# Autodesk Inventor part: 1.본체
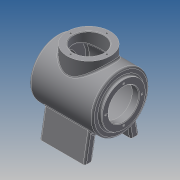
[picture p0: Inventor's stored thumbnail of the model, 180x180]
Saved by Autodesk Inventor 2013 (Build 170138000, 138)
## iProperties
Created: 2015-01
Part Number: 1.본체
Material: Generic
Document SubType Name: Modeling
Designer: kb543-154
Density: 1 g/cm^3
Author: kb543-154
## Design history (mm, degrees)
sketch "스케치1"
  geometry: L1 (-61, 0)-(-61, 38); L2 (-61, 38)-(-56, 38); L3 (-56, 38)-(-56, 50); L4 (-56, 50)-(56, 50); L5 (56, 50)-(56, 38); L6 (56, 38)-(61, 38); L7 (61, 38)-(61, 0); L8 (61, 0)-(-61, 0); 2 further points
  constraints: 16 end point, 5 parallel, 1 coincident, 1 collinear, 1 midpoint, 1 perpendicular, 1 vertical
  dimensions: "d0" = 76 diameter of L2 L8; "d2" = 100 diameter of L4 L8; "d3" = 76 diameter of L6 L8; "d4" = 112 distance of L3.end L4.end; "d5" = 122 distance of L7.end L1.start; "d6" = 5 distance of L1.end L2.end
revolve "회전1" sketch "스케치1" stored, may be unused: angle "d7" = 90 deg
sketch "스케치2"
  geometry: L1 (-61, -38)-(-61, 38) reference; L2 (61, -38)-(61, 38) reference; L3 (-61, 0)-(61, 0); L4 (-61, 27)-(-49, 27); L5 (-56, -50)-(-56, 50) reference; L6 (-49, 27)-(-49, 45); L7 (-49, 45)-(48, 45); L8 (48, 45)-(48, 27); L9 (48, 27)-(61, 27); L10 (56, -50)-(56, 50) reference; 1 further point
  constraints: 12 end point, 3 perpendicular, 2 midpoint, 2 point on line, 1 collinear, 1 parallel, 1 vertical
  dimensions: "d8" = 54 diameter of L4 L3; "d10" = 90 diameter of L7 L3; "d11" = 97 distance between parallel lines of L8 L6; "d12" = 7 horizontal distance of L6.end L5.end
revolve "회전2" sketch "스케치2" stored, may be unused: angle "d13" = 90 deg
sketch "스케치3"
  geometry: L1 (-39.336, -30.865)-(-48, -80); L2 (-48, -80)-(-34, -80); L3 (-34, -80)-(-27.282, -41.901); L4 (27.282, -41.901)-(34, -80); L5 (34, -80)-(48, -80); L6 (48, -80)-(39.336, -30.865); L7 (0, 50)-(0, -50); L8 (-50.903, 0)-(50, 0); 5 further points
  constraints: 16 end point, 3 midpoint, 2 collinear, 2 perpendicular, 1 coincident, 1 horizontal, 1 parallel, 8 other
  dimensions: "d24" = 80 distance from line of L2 point (0, 0); "d25" = 14 distance of L1.end L2.end; "d26" = 14 distance of L4.end L5.end; "d28" = 80 deg angle of L5 L4; "d29" = 100 deg angle of L5 L6; "d30" = 80 deg angle of L2 L3; "d31" = 100 deg angle of L1 L2 (derived); "d32" = 80 distance between parallel lines of L8 L5; "d34" = 69.72143 distance from line of L8.start L4; "d95" = 48 horizontal distance of point (0, 0) L1.end; "d96" = 48 horizontal distance of point (0, 0) L5.end
extrude "돌출1" join sketch "스케치3" stored distance "d35" = 80; taper "d36" = 0 deg
node "작업 평면2"
sketch "스케치7"
  geometry: L1 (21, -10)-(21, -86) reference; C1 r 38 at (-41, -48); 2 further points
  constraints: 1 centre point, 1 horizontal alignment, 1 midpoint
  dimensions: "d39" = 76 diameter of C1; "d41" = 62 distance from line of C1.centre L1
extrude "돌출2" join sketch "스케치7" stored distance "d42" = 80; taper "d43" = 0 deg
hole "구멍1" diameter "d46" = 54; stored, may be unused: countersink angle "d50" = 90 deg, drill point angle "d52" = 118 deg; dims "d44" = 10, "d45" = 10, "d47" = 6, "d48" = 4, "d49" = 2, "d51" = 8
sketch "스케치9"
  geometry: C1 r 27 at (0, 0) reference; 5 further points
  constraints: 1 vertical alignment, 5 other
  dimensions: "d53" = 32 distance of C1.centre point (0, 32); "d56" = 360 deg dimension on C1.centre point (0, 32) (derived)
hole "구멍2" sketch "스케치9" at (-32, 0), (0, -32), (32, 0), (0, 32) diameter "d58" = 3.242; stored, may be unused: countersink angle "d62" = 90 deg, drill point angle "d64" = 118 deg; dims "d59" = 8, "d60" = 4, "d61" = 2, "d63" = 10
sketch "스케치10"
  geometry: C1 r 27 at (0, 0) reference; 4 further points
  constraints: 1 vertical alignment, 5 other
  dimensions: "d65" = 32 distance of C1.centre point (0, 32); "d68" = 360 deg dimension on C1.centre point (0, 32) (derived)
hole "구멍3" sketch "스케치10" at (0, -32), (32, 0), (0, 32), (-32, 0) diameter "d70" = 3.242; stored, may be unused: countersink angle "d74" = 90 deg, drill point angle "d76" = 118 deg; dims "d71" = 8, "d72" = 4, "d73" = 2, "d75" = 10
node "작업 평면4"
  node "작업 평면3"
sketch "스케치13"
  geometry: L1 (-26, 6)-(28, 6); L2 (28, 6)-(28, -6); L3 (28, -6)-(-26, -6); L4 (-26, -6)-(-26, 6); L5 (-61, -38)-(-61, 38) reference; L6 (-37, 62)-(39, 62) reference; L7 (1, 6)-(1, -6); 3 further points
  constraints: 10 end point, 4 midpoint, 2 parallel, 1 horizontal, 1 horizontal alignment, 1 perpendicular
  dimensions: "d82" = 54 distance of L1.start L1.end; "d84" = 12 distance of L3.end L1.start; "d85" = 62 distance between parallel lines of L7 L5
extrude "돌출3" join sketch "스케치13" stored distance "d86" = 80; taper "d87" = 0 deg
sketch "스케치14"
  geometry: L1 (26, -6)-(-28, -6) reference; L2 (26, 6)-(26, -6) reference; 4 further points
  constraints: 2 midpoint, 1 horizontal alignment, 1 vertical alignment, 1 other
feature "엠보싱1" sketch "스케치14" dims "d88" = 0.5, "d89" = 0
fillet "모깎기1" dims "d90" = 3
fillet "모깎기2" dims "d91" = 3
chamfer "모따기1" distance "d92" = 1; stored, may be unused: second distance "d93" = 2, angle "d94" = 45 deg
node "솔리드1"
mirror "대칭1"
other parameters: "d38" = -142, "d81" = 2
